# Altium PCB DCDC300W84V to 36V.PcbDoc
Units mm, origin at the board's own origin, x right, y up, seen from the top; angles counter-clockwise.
Board outline 80 x 58.3 mm, 2 copper layers (Top Layer, Bottom Layer); 51 components, 24 nets, 122 pads, 38 vias.
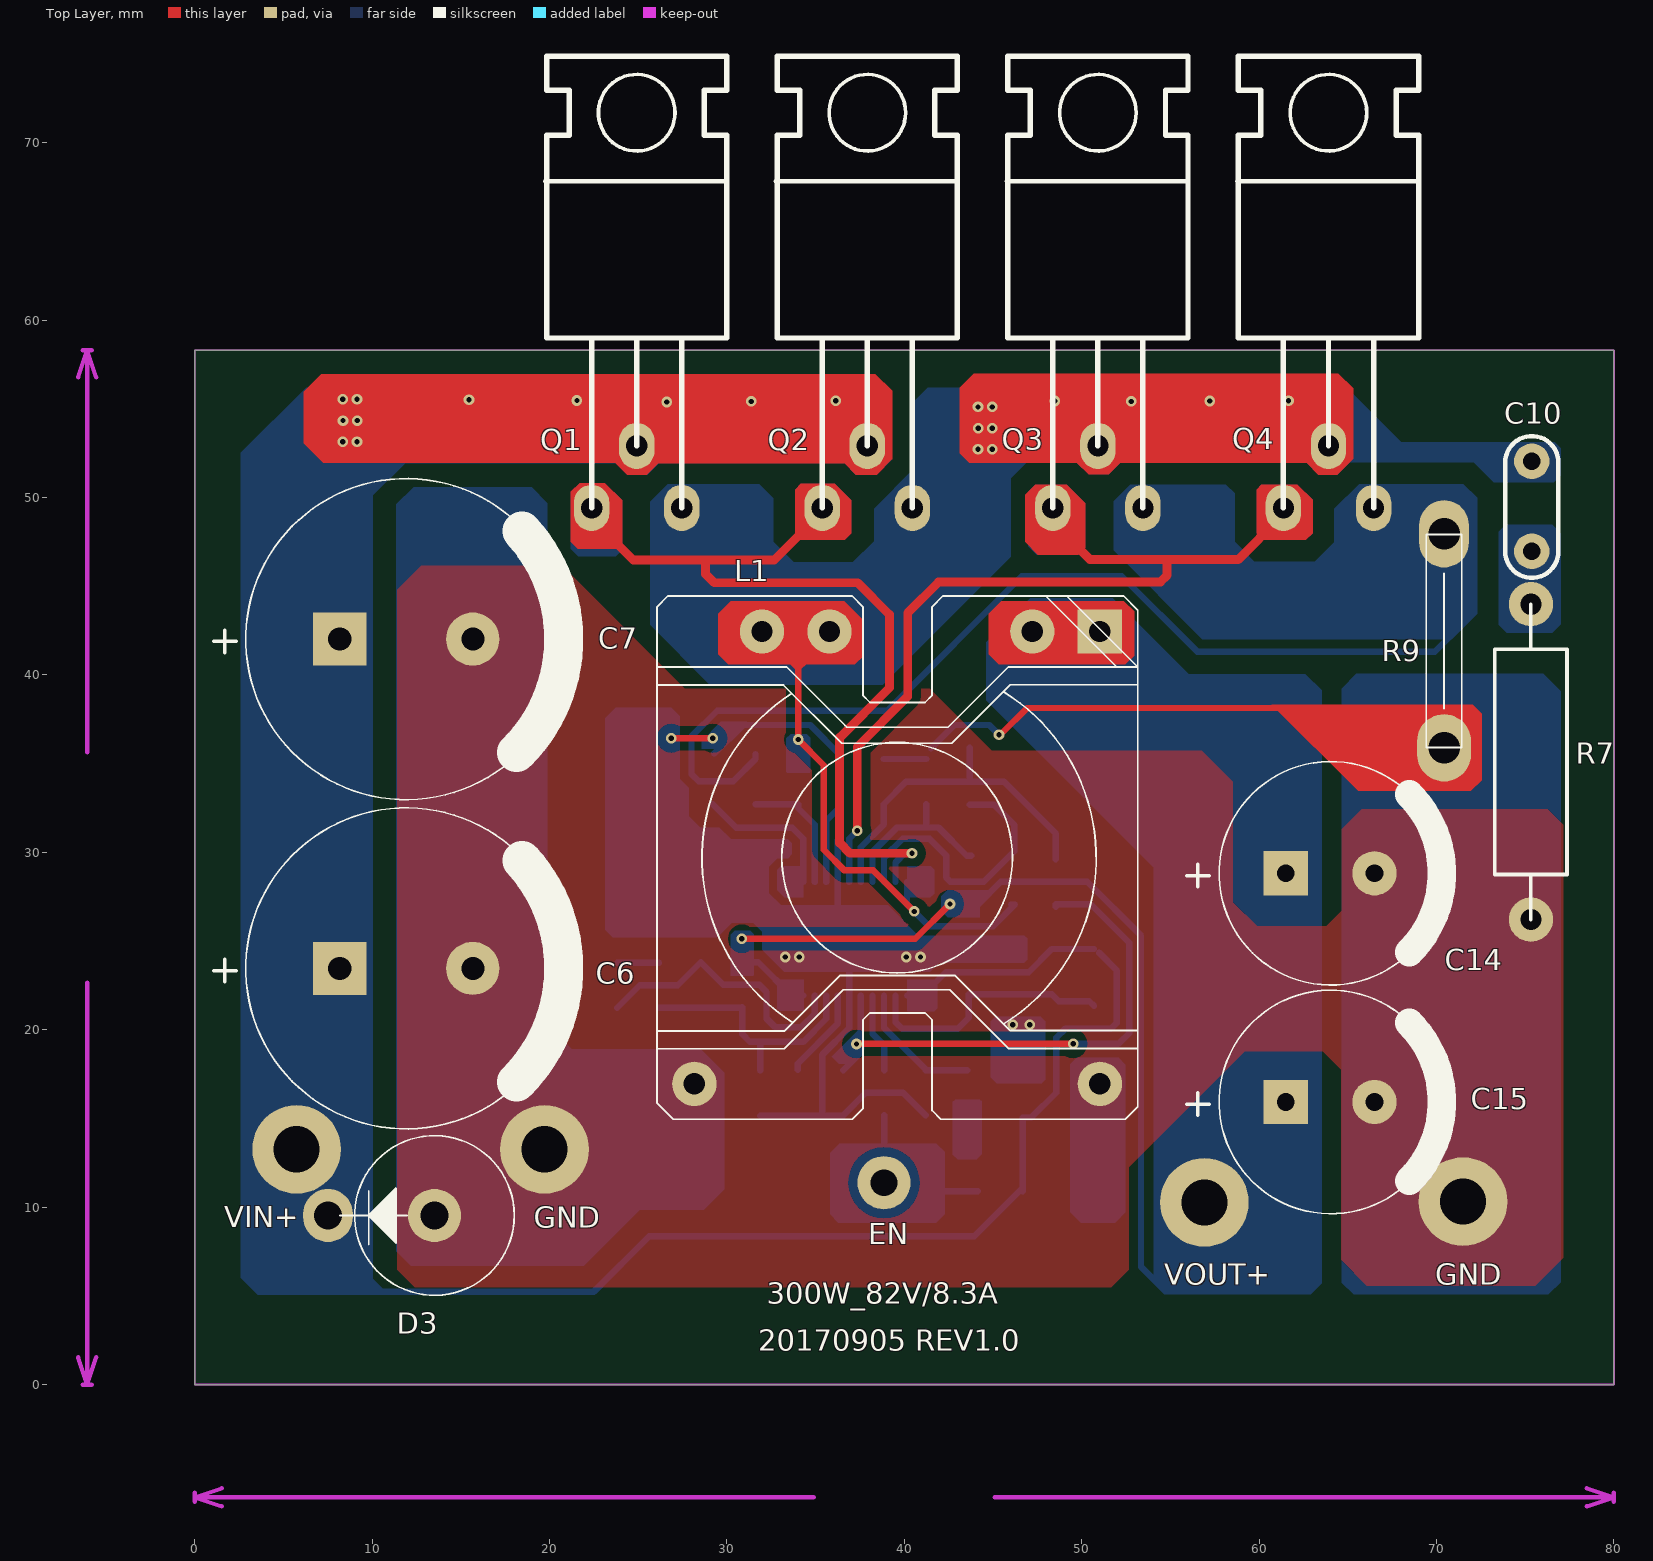
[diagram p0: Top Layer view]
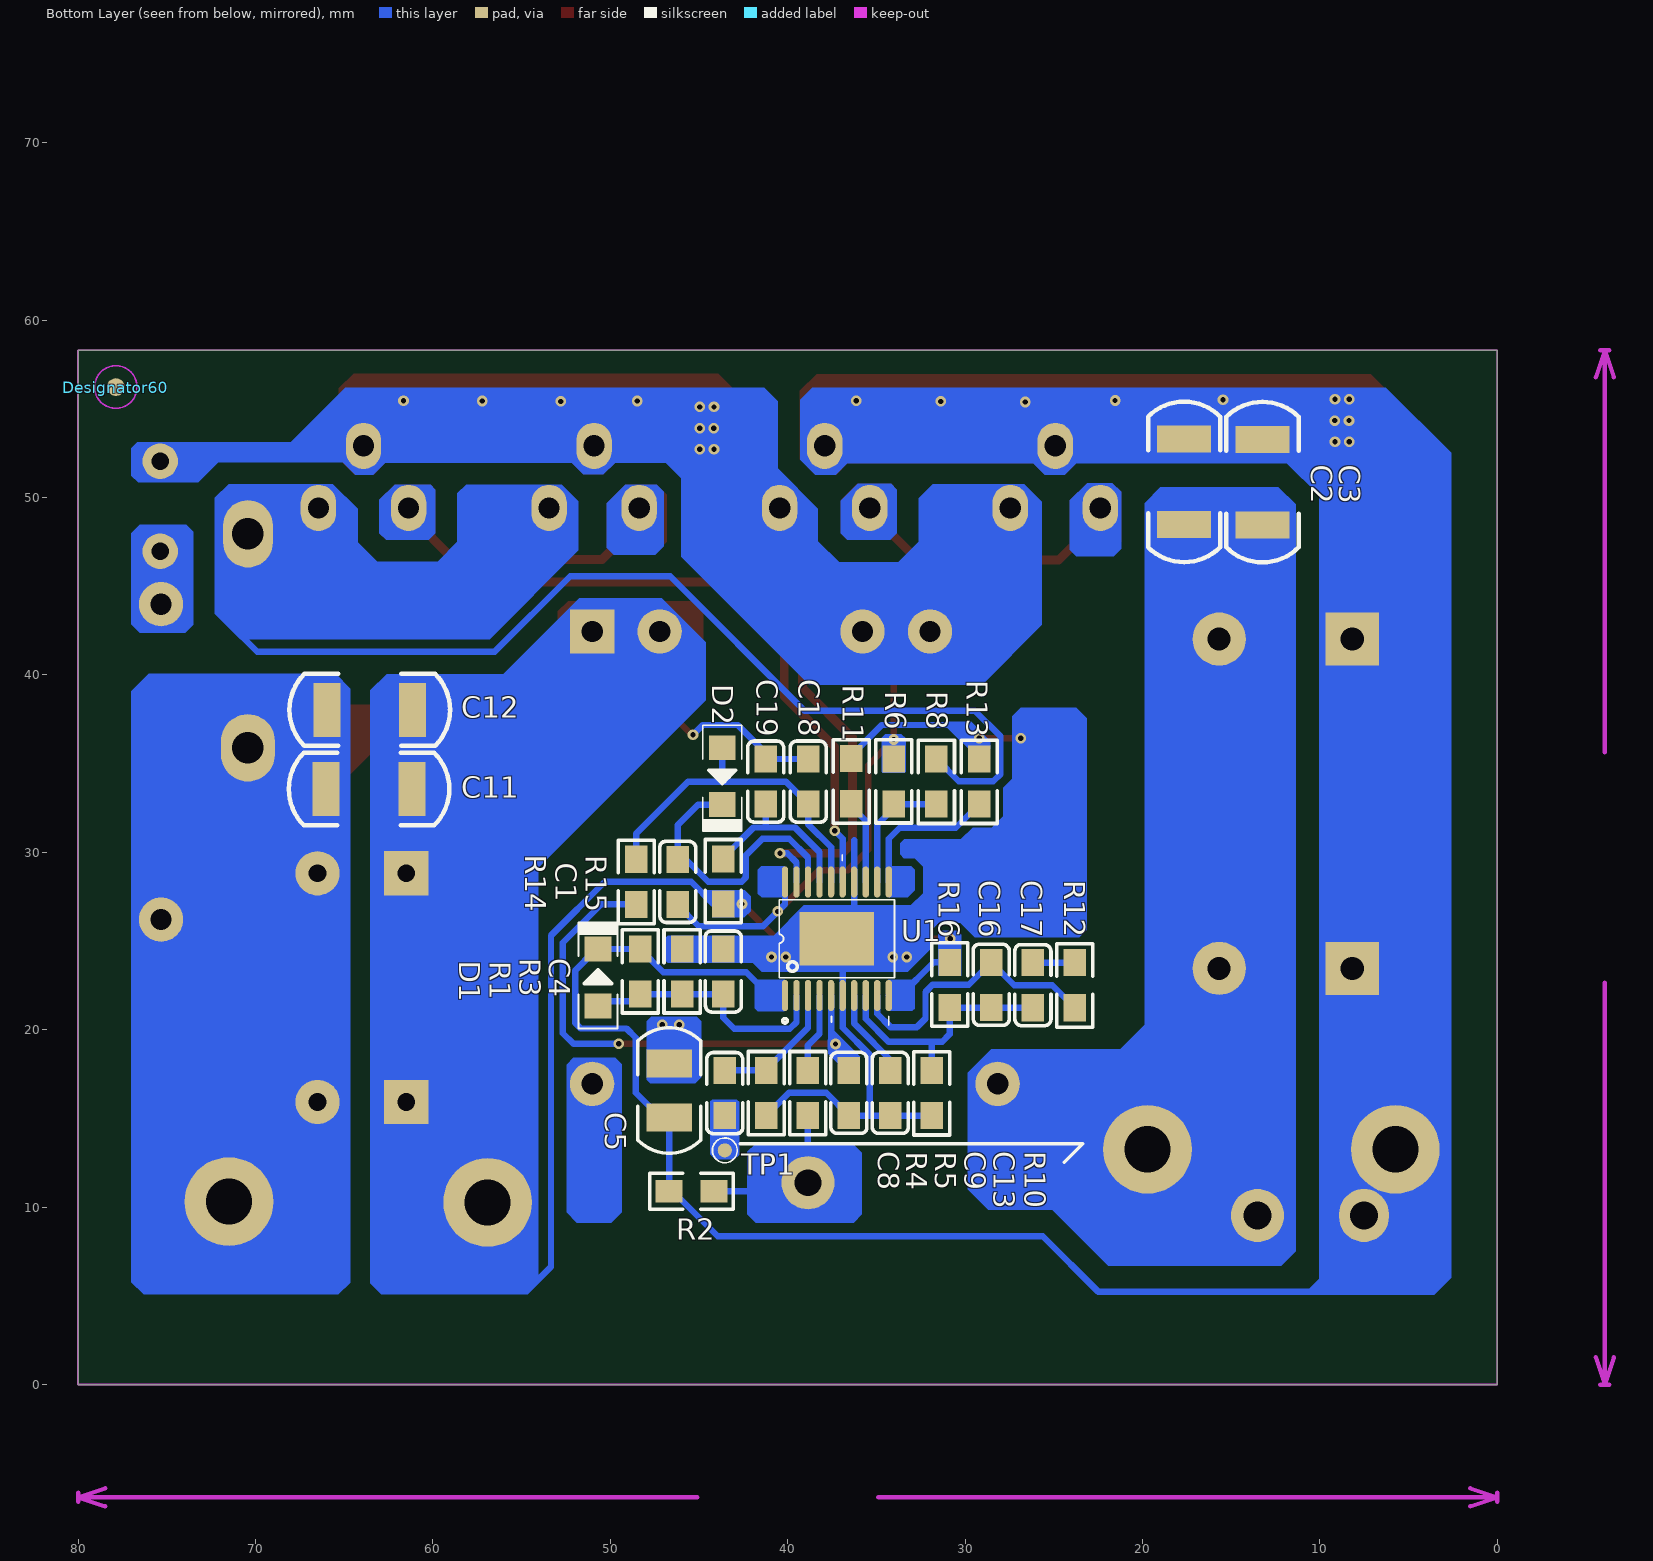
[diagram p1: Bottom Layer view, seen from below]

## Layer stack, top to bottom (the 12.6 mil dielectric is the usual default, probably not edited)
Top Layer: signal copper 0.0356
Dielectric: dielectric 0.32, FR-4, Dk 4.8
Bottom Layer: signal copper 0.0356

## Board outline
0,58.3 0,0 80,0 80,58.3 0,58.3

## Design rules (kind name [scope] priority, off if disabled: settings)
Clearance [All] p1: gap=0.25
ComponentClearance [All] p1: gap=0.254 collisioncheckmode=3 verticalgap=0.254
PlaneConnect [All] p1: planeconnectstyle=Direct reliefexpansion=0.508 reliefentries=4 reliefconductorwidth=0.254 reliefairgap=0.254
PolygonConnect [All] p1: connectstyle=Direct reliefconductorwidth=0.254 reliefentries=4 polygonreliefangle="90 Angle"
RoutingVias [All] p1: holewidth=0.711 width=1.27 viastyle="Through Hole" minholewidth=0.711 minwidth=1.27 maxholewidth=0.711 maxwidth=1.27
SolderMaskExpansion [All] p1: expansion=0.102
TestPointUsage [All] p1: valid=0 allowmultiple=FALSE
Testpoint [All] p1: side=15 testpointundercomponent=TRUE minsize=1.016 maxsize=2.54 preferedsize=1.524 minholesize=0 maxholesize=1.016 preferedholesize=0.813 testpointgrid=0.025 style=1023 order=0123456789
Width [All] p1: maxlimit=10 minlimit=0.254 preferedwidth=0.254
17 further rules are at their usual default settings.

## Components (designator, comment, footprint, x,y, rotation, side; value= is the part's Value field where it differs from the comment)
C1 "1uF/50V" 0805C 46.19,29.6 r270 bottom
C2 "2*2.2uF/100V" 1812C 17.65,48.47 r90 bottom
C3 "4.7uF/100V" 1812C 13.23,48.46 r90 bottom
C4 "100pF/50V" 0805C 43.62,24.55 r270 bottom
C5 "1uF/100V" 1210C 46.67,16.56 r90 bottom
C6 "220uF/200V" EC18 8.17,23.46 r0 top
C7 "220uF/200V" EC18 8.17,42.02 r0 top
C8 "100pF/50V" 0805C 43.55,15.16 r90 bottom
C9 "1nF/50V" 0805C 36.55,15.17 r90 bottom
C10 "222/1KV" CC5B8*3 75.37,46.97 r90 top
C11 "2*4.7uF/50V" 1812C 66.01,33.57 r180 bottom
C12 "4.7uF/100V" 1812C 65.97,38.03 r180 bottom
C13 "33nF/50V" 0805C 34.22,15.17 r90 bottom
C14 "2*1000uF/50V" EC12.5 61.5,28.82 r0 top
C15 "220uF/200V" EC12.5 61.5,15.93 r0 top
C16 "100pF/50V" 0805C 28.52,23.8 r270 bottom
C17 "100nF/50V" 0805C 26.17,23.78 r270 bottom
C18 "1uF/50V" 0805C 38.84,32.72 r90 bottom
C19 "1uF/50V" 0805C 41.24,32.72 r90 bottom
D1 "100V0.25A" SOD-123 50.69,22.87 r90 bottom
D2 "100V0.25A" SOD-123 43.68,34.37 r270 bottom
D3 "6A10" DO-10 13.51,9.53 r180 top
Designator60 "Comment" "Mark point" 77.87,56.23 r180 bottom
EN "14AWG 焊盘" PAD1.8 38.85,11.38 r0 top (schematic designator EN1)
GND "14AWG 焊盘" 14AWG 19.71,13.26 r0 top (schematic designator GND1)
GND "14AWG 焊盘" 14AWG 71.49,10.31 r0 top (schematic designator GND2)
L1 "32uH  1.2mmX46Ts" PQ2620-1 51.02,42.45 r0 top locked
Q1 "2*AOT20N25  250V20A" "TO-220-GDS- W -2" 24.909,52.914 r0 top locked
Q2 "2*AOT20N25  250V20A" "TO-220-GDS- W -2" 37.909,52.914 r0 top locked
Q3 "2*AOT20N25  250V20A" "TO-220-GDS- W -2" 50.909,52.914 r0 top locked
Q4 "2*AOT20N25  250V20A" "TO-220-GDS- W -2" 63.909,52.914 r0 top locked
R1 "237K" 0805R 48.31,24.55 r270 bottom
R2 "0R" 0805R 46.68,10.9 r180 bottom
R3 "9.31K" 0805R 45.95,24.55 r270 bottom
R4 "38.3K" 0805R 41.2,15.17 r90 bottom
R5 "1M" 0805R 38.87,15.17 r90 bottom
R6 "NC" 0805R 34.02,35.26 r270 bottom
R7 "1R" AXIAL-1W-0.7 75.32,35.1 r270 top
R8 "0R" 0805R 31.61,32.72 r90 bottom
R9 "0.01R" 康铜（5mR) 70.47,35.94 r90 top
R10 "1.21K" 0805R 31.87,15.16 r90 bottom
R11 "0R" 0805R 36.42,32.74 r90 bottom
R12 "3.6K" 0805R 23.81,21.24 r90 bottom
R13 "10K" 0805R 29.2,32.72 r90 bottom
R14 "750K" 0805R 48.54,27.07 r90 bottom
R15 "NC" 0805R 43.62,29.63 r270 bottom
R16 "10.7K" 0805R 30.87,23.8 r270 bottom
TP1 "TP" TEST-0.8mm 43.54,13.2 r180 bottom
U1 "IC_LM5116MH" SSOP-20-0.65-1 40.15,21.93 r180 bottom
VIN+ "14AWG 焊盘" 14AWG 5.74,13.26 r0 top
VOUT+ "14AWG 焊盘" 14AWG 56.91,10.27 r0 top

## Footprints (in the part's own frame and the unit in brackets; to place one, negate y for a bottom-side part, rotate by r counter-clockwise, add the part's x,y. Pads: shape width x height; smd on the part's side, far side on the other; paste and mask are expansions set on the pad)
14AWG [mm]
  round 5 hole 2.6: 1(0,0)
0805C [mil]
  rect 60x50 smd: 1(0,0) 2(100,0)
  silkscreen extent -40,-40 140,40
0805R [mil]
  rect 60x50 smd: 1(0,0) 2(100,0)
  silkscreen extent -43,-40 142,40
1210C [mm]
  rect 1.6x2.54 smd: 1(-1.509,0.003) 2(1.539,0.003)
  silkscreen extent -3.51,-1.78 3.54,1.78
1812C [mil]
  rect 60x120 smd: 1(0,0) 2(190,0)
  silkscreen extent -83,-80 273,80
AXIAL-1W-0.7 [mm] "Adjustable Inductor; 2 Leads"
  round 2.5 hole 1.2: 1(-8.89,0) 2(8.89,0)
  silkscreen extent -8.89,-2.03 8.89,2.03
CC5B8*3 [mm]
  round 2 hole 1: 1(0,0) 2(5.08,0)
  silkscreen extent -1.5,-1.5 6.5,1.5
DO-10 [mm]
  round 3 hole 1.6: A(0,0)
  oval 2.8x3 hole 1.6: K(6,0)
  silkscreen extent -4.5,-4.5 5.33,4.5
EC12.5 [mm]
  rect 2.5x2.5 hole 1: 1(0,0)
  round 2.5 hole 1: 2(5,0)
  silkscreen extent -5.59,-6.3 8.84,6.3
EC18 [mm]
  rect 3x3 hole 1.3: 1(0,0)
  round 3 hole 1.3: 2(7.5,0)
  silkscreen extent -7.11,-9.05 12.8,9.05
"Mark point" [mm]
  round 1 smd mask+1: 1(0,0)
  Top Layer keep-out circle w0.1: c0,0 r1.2
PAD1.8 [mm]
  round 3 hole 1.5: 1(0,0)
PQ2620-1 [mm]
  rect 2.5x2.5 hole 1.2: 1(0,0)
  round 2.5 hole 1.2: 2(-3.81,0) 4(-15.24,0) 5(-19.05,0) 7(-22.86,-25.502) 12(0,-25.502)
  silkscreen extent -24.96,-27.5 2.14,2
SOD-123 [mm]
  rect 1.4x1.5 smd: A(-1.524,0) K(1.676,0)
  silkscreen extent -2.79,-1.1 3.2,1.1
SSOP-20-0.65-1 [mm]
  oval 0.36x1.75 smd: 1(0,0) 2(0.65,0) 3(1.3,0) 4(1.95,0) 5(2.6,0) 6(3.25,0) 7(3.9,0) 8(4.55,0) 9(5.2,0) 10(5.85,0) 11(5.85,6.4) 12(5.2,6.4) 13(4.55,6.4) 14(3.9,6.4) 15(3.25,6.4) 16(2.6,6.4) 17(1.95,6.4) 18(1.3,6.4) 19(0.65,6.4) 20(0,6.4)
  rect 4.2x3 smd: 21(2.925,3.2)
  silkscreen extent -0.33,-1.67 6.18,7.92
TEST-0.8mm [mm]
  round 0.8 smd: 1(0,0)
  silkscreen extent -0.7,-0.7 0.7,0.7
"TO-220-GDS- W -2" [mm]
  oval 2x2.6 hole 1.2: D(0,0) G(-2.54,-3.5) S(2.54,-3.5)
  silkscreen extent -5.15,-3.5 5.08,21.97
康铜（5mR) [mm]
  oval 3.8x3.048 hole 1.778: 1(-0.051,0.046)
  oval 3.8x2.8 hole 1.778: 2(12.014,0.046)
  silkscreen extent -0.04,-0.95 11.98,1.05

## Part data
C1 C2 C3 C4 C5 C8 C9 C10 C11 C12 C13 C16 C17 C18 C19: library part CC(DIP)
C6 C7 C14 C15: library part EC
D1 D2 D3: library part DIODE1
EN GND GND VIN+ VOUT+: library part ANT, "ANT"
L1: library part LA
Q1 Q2 Q3 Q4: library part MOSFET-N, "MOS管"
R1 R2 R3 R4 R5 R6 R7 R8 R9 R10 R11 R12 R13 R14 R15 R16: library part RES(SMD)
TP1: library part Test, "测试点"
U1: "集成电路(开关电源)"

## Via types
v1: diameter 0.6, hole 0.3, Top Layer to Bottom Layer, 38 vias

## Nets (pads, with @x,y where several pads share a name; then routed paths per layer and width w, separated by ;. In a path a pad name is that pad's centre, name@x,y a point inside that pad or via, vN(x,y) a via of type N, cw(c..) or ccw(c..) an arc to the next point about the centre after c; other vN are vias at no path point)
GND: C2.1 C3.1 C4.1 C5.2 C6.2 C7.2 C9.1 C11.1 C12.1 C13.1 C14.2 C15.2 C18.2 C19.2 D3.A GND.1 L1.7 L1.12 R3.1 R4.1 R7.2 R9.1 R10.1 R11.2 R13.2 U1.6 U1.14 U1.21 | length 80.5
  Top Layer w0.36: v1(26.86,36.43) v1(29.2,36.43) ; v1@45.52,36.74 46.92,38.14 62.61,38.14 ; R9.1@69.69,36.623 R9.1
  Bottom Layer w0.36: 29.01,30.08 33.85,25.24 U1.21@36.1,25.24 ; R13.2@29.29,35.57 30.9,37.18 34.69,37.18 R11.2@36.42,35.45 ; R10.1 C9.1@36.54,15.16 ; 35.38,15.16 35.38,18.6 36.9,20.12 U1.21@36.9,24.51 ; U1.21@36.25,25.85 36.25,30.69 ; R11.2 R11.2@36.42,35.57 ; C9.1 37.83,16.45 39.92,16.45 R4.1 ; U1.21@36.72,24.55 R3.1 ; C18.2 C19.2 ; C19.2@41.5,35.87 42.81,37.18 44.78,37.18 v1(45.337,36.623) ; C5.2@47.06,18.15 C5.2@47.13,18.22 ; v1@47.12,20.18 v1@47.13,20.17
  other v1: 46.11,20.29 47.06,20.29 33.28,24.1 34.08,24.1 40.11,24.1 40.91,24.1
NetC1_1: C1.1 D2.K U1.18 | length 16.1
  Bottom Layer w0.36: U1.18 38.85,29.71 39.9,30.76 41.42,30.76 42.36,29.82 42.36,28.58 42.59,28.35 44.48,28.35 46.19,30.06 46.19,31.54 45.036,32.694 D2.K
NetC1_2: C1.2 C10.2 L1.4 L1.5 Q1.S Q2.S Q3.D Q4.D R6.1 U1.20 | length 26.9
  Top Layer w0.36: 34.01,41.39 v1(34.01,36.36) 35.46,34.91 35.46,30.14 36.62,28.98 38.25,28.98 v1(40.56,26.67)
  Bottom Layer w0.36: U1.20 40.15,27.08 41.39,25.84 45.01,25.84 46.23,27.06 C1.2@46.03,27.06
  other v1: 44.15,52.72 44.95,52.72 44.16,53.91 44.96,53.91 44.15,55.11 44.95,55.11 52.79,55.42 48.48,55.44 57.22,55.44 61.65,55.46
NetC4_2: C4.2 D1.A R1.2 R3.2 U1.2 | length 14.7
  Bottom Layer w0.36: U1.2 39.5,20.43 39.88,20.05 43,20.05 43.62,20.67 C4.2 R1.2 48.71,21.61 50.426,21.61 D1.A
NetC8_1: C8.1 TP1.1
NetC8_2: C8.2 R4.2 U1.3 | length 7.5
  Bottom Layer w0.36: U1.3 38.85,20.11 41.2,17.76 R4.2 C8.2@43.54,17.71
NetC9_2: C9.2 R14.1 U1.5 | length 30.5
  Top Layer w0.36: v1(37.3,19.2) v1(49.511,19.208)
  Bottom Layer w0.36: C9.2 37.55,18.71 U1.5 ; R14.1@48.54,26.94 R14.1 50.51,27.07 52.67,24.91 52.67,19.81 52.068,19.208 v1(49.511,19.208)
NetC10_1: C10.1 R7.1
NetC13_2: C13.2 U1.7 | length 5.1
  Bottom Layer w0.36: C13.2@33.99,17.74 33.99,18.09 36.25,20.35 U1.7
NetC16_1: C16.1 R12.1 U1.9 | length 15.9
  Bottom Layer w0.36: R12.1 25.08,22.51 27.23,22.51 C16.1 29.79,22.53 31.83,22.53 32.23,22.13 32.23,20.63 32.71,20.15 34.2,20.15 34.95,20.9 U1.9
NetC16_2: C16.2 C17.2 R10.2 R16.2 U1.8 | length 14.6
  Bottom Layer w0.36: C17.2 R16.2@30.85,21.24 ; R16.2 30.87,19.75 31.29,19.33 34.31,19.33 35.6,20.62 U1.8 ; R10.2 31.87,19.23 31.97,19.33
NetC17_1: C17.1 R12.2 | length 2.4
  Bottom Layer w0.36: R12.2 C17.1
NetC18_1: C18.1 D2.A R14.2 U1.16 | length 19.7
  Bottom Layer w0.36: U1.16 37.55,30.28 38.84,31.57 C18.1 40.11,33.99 45.61,33.99 48.54,31.06 R14.2 ; 43.68,34.01 D2.A
NetC19_1: C19.1 R15.1 U1.17 | length 9.8
  Bottom Layer w0.36: U1.17 38.2,30.02 39.58,31.4 41.92,31.4 43.52,29.8 R15.1@43.76,29.8 ; 41.24,31.41 C19.1
NetEN1_1: EN.1 R2.2 R5.1 | length 7.1
  Bottom Layer w0.36: EN.1@38.87,11.92 R5.1 ; EN.1@40.25,10.9 R2.2
NetQ1_G: Q1.G Q2.G U1.19 | length 48.2
  Top Layer w0.5: Q1.G 22.369,48.831 24.73,46.47 32.65,46.47 Q2.G@35.25,49.07 ; 28.78,46.47 28.78,45.7 29.28,45.2 37.36,45.2 39.16,43.4 39.16,39.28 36.35,36.47 36.35,30.53 36.93,29.95 v1(40.43,29.95)
  Bottom Layer w0.36: U1.19 39.5,29.43 40.02,29.95 v1(40.43,29.95)
NetQ3_G: Q3.G Q4.G U1.15 | length 48.4
  Top Layer w0.5: v1(37.34,31.21) 37.34,35.94 40.19,38.79 40.19,43.5 41.93,45.24 54.43,45.24 54.81,45.62 54.81,46.5 ; Q3.G 48.369,48.601 50.47,46.5 58.82,46.5 Q4.G@61.2,48.88
  Bottom Layer w0.36: U1.15 36.9,30.77 v1(37.34,31.21)
NetQ3_S: Q3.S Q4.S R8.2 R9.2 | length 56.2
  Bottom Layer w0.36: R8.2@31.61,35.53 R8.2 30.35,34 28.41,34 28,34.41 28,36.54 29.45,37.99 39.05,37.99 46.62,45.56 52.26,45.56 56.52,41.3 69.9,41.3 70.83,42.23 70.83,43.04
NetR5_2: R5.2 U1.4 | length 4.5
  Bottom Layer w0.36: U1.4 38.2,19.78 38.87,19.11 R5.2
NetR6_2: R6.2 R8.1 U1.12 | length 7
  Bottom Layer w0.36: R8.1 R6.2@33.86,32.72 ; R6.2 34.02,32.49 34.95,31.56 U1.12
NetR11_1: R11.1 U1.13 | length 4.7
  Bottom Layer w0.36: U1.13 35.6,31.78 36.42,32.6 R11.1
NetR13_1: R13.1 U1.11 | length 8.3
  Bottom Layer w0.36: R13.1 30.53,31.39 33.67,31.39 34.3,30.76 U1.11
VIN+: C2.2 C3.2 C5.1 C6.1 C7.1 D1.K D3.K Q1.D Q2.D R1.1 R2.1 U1.1 VIN+.1 | length 68.6
  Bottom Layer w0.36: 9.88,5.24 22.5,5.24 25.61,8.35 43.94,8.35 R2.1@46.68,11.09 ; U1.1 41.01,21.93 42.33,23.25 47.01,23.25 R1.1 D1.K@50.686,24.55 ; R2.1 C5.1@46.68,15.044 ; C5.1@46.743,15.051 47.161,15.051 48.56,16.45 48.56,19.55 49.08,20.07 51.67,20.07 51.98,20.38 51.98,23.34 D1.K@50.97,24.35
  other v1: 8.34,53.15 9.14,53.15 8.35,54.34 9.15,54.34 26.6,55.39 31.37,55.42 36.14,55.45 21.54,55.47 15.46,55.52 8.34,55.54 9.14,55.54
VOUT+: C11.2 C12.2 C14.1 C15.1 L1.1 L1.2 R15.2 R16.1 U1.10 VOUT+.1 | length 51.7
  Top Layer w0.36: v1(30.84,25.13) 40.61,25.13 v1(42.57,27.09)
  Bottom Layer w0.36: R16.1@30.84,23.83 v1(30.84,25.13) ; R16.1 31.77,23.8 33.64,21.93 U1.10 ; R15.2 44.18,27.09 45.43,28.34 50.31,28.34 53.34,25.31 53.34,6.64 54.2,5.78 56.48,5.78
pads on no net: Designator60.1

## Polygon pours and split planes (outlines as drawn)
GND on Top Layer "Top Layer-No Net" (solid, remove dead copper, pour order 1000): 65.79,32.43 64.66,31.3 64.66,26.71 63.78,25.83 59.88,25.83 58.52,27.19 58.52,33.97 56.75,35.74 44.93,35.74 41.44,39.23 27.62,39.23 20.7,46.15 12.77,46.15 11.41,44.79 11.41,6.48 12.4,5.49 51.67,5.49 52.66,6.48 52.66,12.26 59.18,18.78 63.58,18.78 64.62,17.74 64.62,7.02 66.06,5.58 75.57,5.58 77.14,7.15 77.14,31.56 76.27,32.43

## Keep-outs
Keep-Out Layer:
  lines w0.1: 0,0 80,0 80,58.3 0,58.3 0,0
  lines w0.254: -6.582,1.524 -6.074,0 ; -6.582,56.776 -6.074,58.3 ; -6.328,0 -5.82,0 ; -6.328,58.3 -5.82,58.3 ; -6.074,22.65 -6.074,0 ; -6.074,35.65 -6.074,58.3 ; -5.566,1.524 -6.074,0 ; -5.566,56.776 -6.074,58.3 ; 0,-6.618 0,-6.11 ; 1.524,-6.872 0,-6.364 ; 1.524,-5.856 0,-6.364 ; 34.897,-6.364 0,-6.364 ; 45.103,-6.364 80,-6.364 ; 78.476,-6.872 80,-6.364 ; 78.476,-5.856 80,-6.364 ; 80,-6.618 80,-6.11
  text "58.3 (mm)" at -5.16,22.904 h1.52 r90
  text "80 (mm)" at 35.151,-7.278 h1.52

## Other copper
Top Layer:
  region net NetC1_2: 33.885,40.265 34.21,40.59 33.807,40.993 33.482,40.668
  region net NetC1_2: 34.535,40.665 34.21,40.99 33.807,40.587 34.132,40.262
  region net NetQ1_G: 21.2,50.33 21.69,50.82 23.11,50.82 24.09,49.84 24.09,47.26 23.94,47.11 21.59,47.11 21.2,47.5
  region net NetQ1_G: 34.17,50.77 33.85,50.45 33.85,47.82 34.05,47.62 36.63,47.62 37.01,48 37.01,49.84 36.08,50.77
  region net NetQ3_G: 47.39,50.73 49.14,50.73 50.2,49.67 50.2,47.17 49.81,46.78 47.53,46.78 46.81,47.5 46.81,50.15
  region net NetQ3_G: 60.12,50.72 59.85,50.45 59.85,47.99 60.22,47.62 62.63,47.62 63.01,48 63.01,49.87 62.16,50.72
  region net NetC1_2: 30.22,44.16 29.51,43.45 29.51,41.16 30.08,40.59 37.21,40.59 37.71,41.09 37.71,43.05 36.6,44.16
  region net VOUT+: 45.46,44.16 44.75,43.45 44.75,41.16 45.32,40.59 52.45,40.59 52.95,41.09 52.95,43.59 52.38,44.16
  region net VIN+: 36.63,51.94 37.27,51.3 38.45,51.3 39.3,52.15 39.31,52.15 39.31,56.01 38.36,56.96 7.13,56.96 6.14,55.97 6.14,53.06 7.24,51.96 23.71,51.96 24.39,51.28 25.47,51.28 26.12,51.93 36.62,51.93
  region net NetC1_2: 49.72,51.97 50.38,51.31 51.51,51.31 52.17,51.97 62.67,51.97 63.34,51.3 64.4,51.3 65.3,52.2 65.3,56.15 64.47,56.98 43.9,56.98 43.12,56.2 43.12,52.5 43.65,51.97
  region net GND: 72.55,37.81 72.04,38.32 60.72,38.32 65.58,33.46 71.94,33.46 72.55,34.07
Bottom Layer:
  region net VIN+: 10.283,5.117 10.588,5.422 9.985,6.025 9.68,5.72
  region net NetC10_1: 76.99,48 76.52,48.47 73.89,48.47 73.5,48.08 73.5,42.83 73.955,42.375 76.515,42.375 76.99,42.85
  region net NetC1_2: 34.7,34.54 34.7,36.46 34.49,36.67 33.59,36.67 33.34,36.42 33.34,34.55 33.39,34.5 34.66,34.5
  region net NetEN1_1: 41.81,13.57 36.32,13.57 35.81,13.06 35.81,9.59 36.28,9.12 41.8,9.12 42.27,9.59 42.27,13.11
  region net NetC8_1: 42.87,16.06 42.74,15.93 42.74,12.95 43,12.69 44.07,12.69 44.35,12.97 44.35,15.96 44.25,16.06
  region net VIN+: 10.03,5.18 10.03,50.12 11.85,51.94 23.73,51.94 24.39,51.28 25.5,51.28 26.16,51.94 36.64,51.94 37.3,51.28 38.44,51.28 39.3,52.14 39.3,55.52 38.62,56.2 6.27,56.2 2.6,52.53 2.6,6.02 3.56,5.06 9.91,5.06
  region net GND: 11.36,7.5 11.36,49.62 12.33,50.59 18.98,50.59 19.88,49.69 19.88,18.43 23.08,15.23 23.08,7.85 21.92,6.69 12.17,6.69
  region net VOUT+: 47.1,44.33 51.75,44.33 56.03,40.05 62.61,40.05 63.53,39.13 63.53,5.71 62.91,5.09 54.64,5.09 54.06,5.67 54.06,29.12 44.62,38.56 44.62,41.85
  region net GND: 64.65,39.23 65.48,40.06 76.02,40.06 76.99,39.09 76.99,5.77 76.3,5.08 65.32,5.08 64.65,5.75
  region net GND: 31.1,37.36 29.66,37.36 28.57,36.27 28.57,35.85 29.59,35.85
  region net NetQ1_G: 34.17,50.77 33.85,50.45 33.85,47.99 34.22,47.62 36.63,47.62 37.01,48 37.01,49.82 36.06,50.77
  region net NetQ3_S: 52.72,50.72 58.12,50.72 58.61,50.23 58.61,47.5 59.73,46.38 63.13,46.38 64.24,47.49 64.24,49.36 65.64,50.76 71.51,50.76 72.29,49.98 72.29,43.44 70.87,42.02 56.8,42.02 51.79,47.03 51.79,49.79
  region net NetC1_2: 25.67,49.75 25.67,42.82 29.04,39.45 38.78,39.45 45.99,46.66 45.99,51.08 46.88,51.97 49.72,51.97 50.38,51.31 51.51,51.31 52.17,51.97 62.67,51.97 63.35,51.29 64.38,51.29 65.085,51.995 72.095,51.995 73.22,50.87 76.62,50.87 76.99,51.24 76.99,52.79 76.65,53.13 68,53.13 64.93,56.2 41.33,56.2 40.56,55.43 40.56,51.64 38.29,49.37 38.29,47.54 37.09,46.34 33.77,46.34 32.6,47.51 32.6,49.97 31.83,50.74 26.66,50.74
  region net GND: 23.08,7.85 25.09,9.86 28.7,9.86 29.84,11 29.84,17.58 28.53,18.89 21.25,18.89 18.6,21.54 18.6,12.33
  region net NetC9_2: 37.73,19.44 37.73,18.89 36.91,18.07 36.31,18.07 35.91,18.47 37.54,20.1 37.55,20.1 37.55,19.62
  region net VOUT+: 34.32,22.81 32.95,22.81 32.84,22.92 32.84,21.19 32.97,21.06 34.3,21.06 34.32,21.08
  region net NetR13_1: 34.3,29.21 33.03,29.21 32.83,29.01 32.83,27.85 33.22,27.46 34.3,27.46
  region net VOUT+: 31.5,25.38 31.3,25.58 30.44,25.58 30.22,25.36 30.22,23.05 30.23,23.04 31.48,23.04 31.5,23.06
  region net VOUT+: 44.94,27.85 44.33,27.24 44.26,27.24 44.26,26.34 44.25,26.33 42.45,26.33 42.09,26.69 42.09,27.52 42.42,27.85
  region net GND: 49.71,18.42 49.34,18.05 49.34,9.71 49.93,9.12 51.88,9.12 52.46,9.7 52.46,18.04 52.08,18.42
  region net GND: 47.94,20.47 47.69,20.72 45.11,20.72 44.86,20.47 44.86,17.31 45.2,16.97 47.73,16.97 47.94,17.18
  region net NetC1_2: 40.15,29.21 41.48,29.21 41.68,29.01 41.68,27.67 41.47,27.46 40.16,27.46 40.15,27.45 40.15,29.21
  region net VIN+: 40.15,22.81 41.84,22.81 41.84,21.22 41.67,21.05 40.18,21.05 40.15,21.08
  region net GND: 46.77,25.31 46.93,25.15 46.93,23.95 46.77,23.79 41.97,23.79 41.45,23.27 33.22,23.27 31.98,24.51 31.98,25.52 31.48,26.02 30.27,26.02 29.46,25.21 23.57,25.21 23.15,25.63 23.15,37.57 23.72,38.14 26.87,38.14 27.34,37.67 27.34,34.15 27.85,33.64 27.85,32.04 28.49,31.4 29.57,31.4 30.24,30.73 33.43,30.73 33.66,30.5 33.66,29.88 33.44,29.66 32.84,29.66 32.36,29.18 32.36,27.7 33.05,27.01 39.08,27.01 40.78,25.31
  region net NetQ1_G: 21.2,50.33 21.69,50.82 23.11,50.82 24.09,49.84 24.09,47.05 23.74,46.7 21.61,46.7 21.2,47.11
  region net NetQ3_G: 60.12,50.72 59.85,50.45 59.85,47.99 60.22,47.62 62.63,47.62 63.01,48 63.01,49.87 62.16,50.72
  region net NetQ3_G: 47.39,50.73 49.14,50.73 50.2,49.67 50.2,47.17 49.81,46.78 47.46,46.78 46.98,47.26 46.98,50.32

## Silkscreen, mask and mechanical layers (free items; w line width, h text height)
Top Overlay:
  text "300W_82V/8.3A" at 32.24,4.56 h1.2
  text "20170905 REV1.0" at 31.75,1.89 h1.2
Bottom Overlay:
  lines w0.2: 24.405,12.535 23.37,13.57 42.67,13.57
Bottom Solder:
  region: 40.145,21.08 41.245,21.08 41.445,21.28 41.445,22.58 41.245,22.78 40.155,22.78
  region: 40.155,27.48 41.255,27.48 41.455,27.68 41.455,28.98 41.255,29.18 40.165,29.18
  region: 35.24,55.8 35.24,52.32 34.97,52.05 32.54,52.05 32.23,52.36 32.23,55.83 32.46,56.06 34.98,56.06
  region: 30.56,55.8 30.56,52.32 30.29,52.05 27.86,52.05 27.55,52.36 27.55,55.83 27.78,56.06 30.3,56.06
  region: 60.92,55.805 60.92,52.325 60.65,52.055 58.22,52.055 57.91,52.365 57.91,55.835 58.14,56.065 60.66,56.065
  region: 56.5,55.79 56.5,52.31 56.23,52.04 53.8,52.04 53.49,52.35 53.49,55.82 53.72,56.05 56.24,56.05
  region: 62.77,45.59 66.25,45.59 66.52,45.32 66.52,42.89 66.21,42.58 62.74,42.58 62.51,42.81 62.51,45.33
  region: 57.3,45.62 60.78,45.62 61.05,45.35 61.05,42.92 60.74,42.61 57.27,42.61 57.04,42.84 57.04,45.36
  region: 34.28,29.19 33.18,29.19 32.98,28.99 32.98,27.69 33.18,27.49 34.27,27.49
  region: 34.29,22.78 33.18,22.78 32.97,22.57 32.97,21.25 33.15,21.07 34.29,21.07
